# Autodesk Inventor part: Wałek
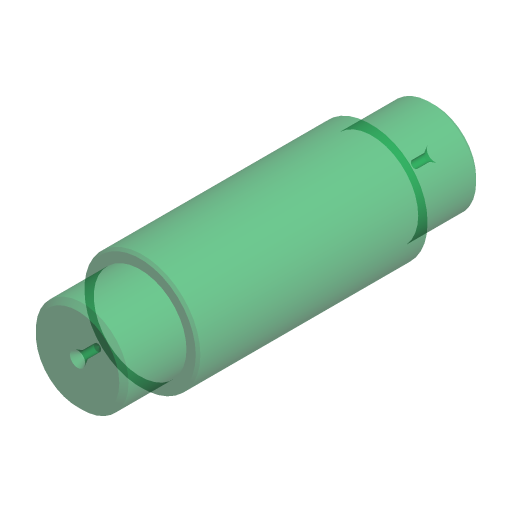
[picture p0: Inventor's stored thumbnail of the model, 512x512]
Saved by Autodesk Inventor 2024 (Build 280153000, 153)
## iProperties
Company: ATC
Shininess: 20.0
Length Units: 11269
Angle Units: 11279
Time Units: 11290
Mass Units: 11283
Length Display Precision: 3
Angle Display Precision: 2
Compacted: True
Created: 2023-03
Part Number: Wałek
Document SubType Name: Modeling
Designer: Andrzej Jaskulski
Density: 1 g/cm^3
Material: Ogólny
Appearance: Green(Clear)
Checked By: A.J.
Engr Approved By: Andrzej Jaskulski
Mfg Approved By: Andrzej Jaskulski
Authority: A.J.
Density: 0.0
Volumn: 0.0
Area: 0.0
PropertySet Name: Model Information
Control State: 0
Master: False
Checked Out: False
Title: A.J.: Kurs R2024-MEP
Author: Andrzej Jaskulski
Revision Number: 1/24
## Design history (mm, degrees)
workplane "Work Plane2"
node "Hole1" dims "d9" = 1.6, "d10" = 3.35, "d11" = 2, "d12" = 60 deg, "d13" = 4.3, "d14" = 120 deg, "d30" = 6
node "Mirror1"
node "Chamfer1" dims "d15" = 1, "d16" = 1, "d31" = 45 deg
node "Chamfer2" dims "d17" = 0.5, "d18" = 0.5, "d32" = 45 deg
node "Bryła1"
  node "Extrusion1" dims "d1" = 50, "d2" = 0
  node "Extrusion2" dims "d5" = 13.5, "d6" = 0
workaxis "Work Axis1"
node "Korpusy bryłowe"
node "Korpusy powierzchniowe"
sketch "Sketch1"
  geometry: C1 r 12.5 at (0, 0)
  constraints: 1 centre point
  dimensions: "d3" = 25 diameter of C1
sketch "Sketch2"
  geometry: C1 r 12.5 at (0, 0) reference; C2 r 10 at (0, 0)
  constraints: 1 centre point, 1 coincident
  dimensions: "d4" = 20 diameter of C2
sketch "Sketch3"
  geometry: C1 r 10 at (0, 0) reference; 1 further point
  constraints: 1 coincident
other parameters: "d8" = -25, "d24" = 45 (derived)
